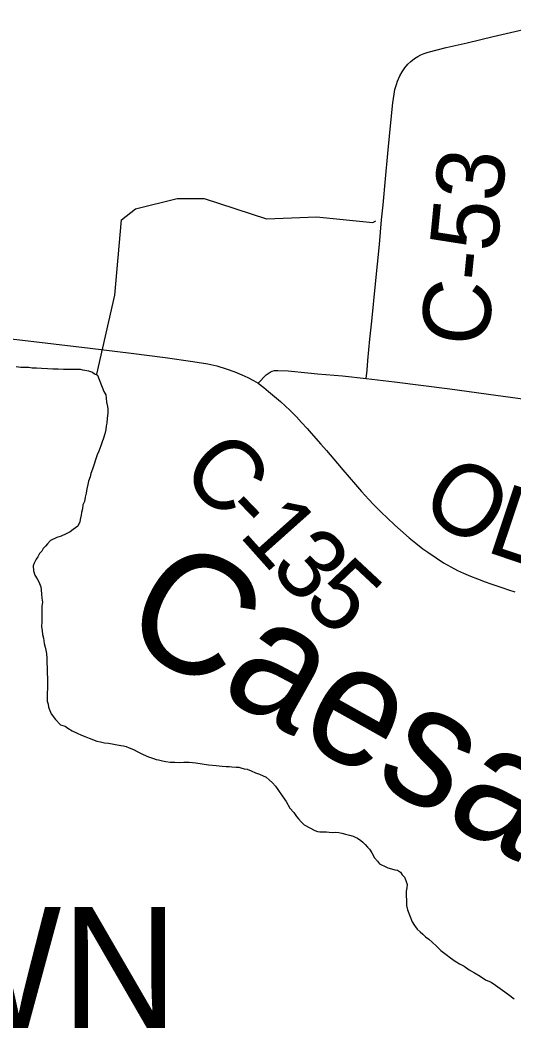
# Model space of a CAD drawing. Extents: x -13.9 to 69.1, y -25.2 to 26.1.
# Drawn here: x 4.71 to 5.08, y 17.195 to 17.95 of the extents above; entities that cross this region are included whole.
import ezdxf

# ---------------------------------------------------------------- set-up
doc = ezdxf.new("R2010")
doc.units = 0
for name, color, linetype in [('GM_X_Corporation_Text', 7, 'Continuous'), ('GM_X_County_Road', 7, 'Continuous'), ('GM_X_County_Road_Text', 7, 'Continuous'), ('GM_X_Minor_River', 7, 'Continuous'), ('GM_X_Minor_River_Text', 7, 'Continuous'), ('GM_X_State_Route', 7, 'Continuous')]:
    doc.layers.add(name, color=color, linetype=linetype)

msp = doc.modelspace()

# ---------------------------------------------------------------- linework, layer by layer
at = {"layer": 'GM_X_County_Road'}
for points in [[(4.9692, 17.68197), (4.9698, 17.68831), (4.97048, 17.69539), (4.97188, 17.71138), (4.97324, 17.72498), (4.97607, 17.75276), (4.97919, 17.78228), (4.98071, 17.80064), (4.98175, 17.81189), (4.98358, 17.83141), (4.98531, 17.85035), (4.98714, 17.86864), (4.98907, 17.88818), (4.99002, 17.8947), (4.99069, 17.89833), (4.99171, 17.90191), (4.99258, 17.90459), (4.99429, 17.90843), (4.99605, 17.91156), (4.99808, 17.91449), (5.00038, 17.91718), (5.00247, 17.91922), (5.00523, 17.9214), (5.0077, 17.9229), (5.0101, 17.92409), (5.01253, 17.92512), (5.01552, 17.92614), (5.02904, 17.92954), (5.04471, 17.93326), (5.06415, 17.93779), (5.11709, 17.9501)], [(4.88821, 17.67846), (4.89262, 17.67523), (4.89609, 17.67235), (4.89904, 17.66983), (4.90211, 17.66735), (4.90506, 17.66475), (4.90884, 17.66133), (4.91209, 17.65815), (4.91688, 17.65326), (4.92077, 17.64908), (4.92506, 17.64447), (4.92807, 17.64102), (4.93522, 17.63278), (4.9394, 17.62803), (4.94763, 17.61843), (4.95172, 17.61361), (4.96102, 17.60262), (4.96559, 17.59743), (4.97103, 17.59148), (4.97464, 17.58778), (4.9807, 17.58166), (4.98482, 17.57768), (4.99063, 17.57217), (4.99488, 17.56834), (5.00136, 17.56273), (5.00623, 17.55879), (5.01163, 17.55461), (5.01531, 17.55194), (5.02138, 17.54774), (5.0271, 17.54408), (5.03246, 17.54092), (5.03749, 17.53835), (5.04207, 17.53621), (5.04723, 17.53402), (5.05242, 17.53194), (5.05817, 17.52978), (5.06237, 17.52826), (5.06764, 17.52647), (5.07133, 17.52522), (5.07556, 17.52382), (5.08032, 17.52224)]]:
    msp.add_lwpolyline(points, dxfattribs=at)
at = {"layer": 'GM_X_Minor_River'}
for points in [[(4.76764, 17.68523), (4.78099, 17.74442), (4.78597, 17.80068), (4.79655, 17.80883), (4.8277, 17.81658), (4.84793, 17.81654), (4.89454, 17.80145), (4.93198, 17.8029), (4.97406, 17.7988), (4.97643, 17.79985)], [(4.70726, 17.69092), (4.71063, 17.69051), (4.71367, 17.69048), (4.71671, 17.69044), (4.71907, 17.69005), (4.72244, 17.69001), (4.72615, 17.6896), (4.73054, 17.68954), (4.73458, 17.68913), (4.73863, 17.68908), (4.74268, 17.68903), (4.74606, 17.68899), (4.74943, 17.68895), (4.75247, 17.68892), (4.75517, 17.68888), (4.75686, 17.6885), (4.75854, 17.68812), (4.76124, 17.68772), (4.76426, 17.68659), (4.76594, 17.68548), (4.76795, 17.68437), (4.7729, 17.6723), (4.77422, 17.66974), (4.77454, 17.66719), (4.77485, 17.66428), (4.77549, 17.661), (4.77581, 17.65918), (4.77577, 17.6559), (4.7754, 17.65227), (4.77503, 17.64864), (4.77467, 17.64646), (4.77431, 17.64392), (4.7736, 17.64066), (4.77255, 17.63739), (4.77151, 17.6345), (4.77047, 17.6316), (4.76908, 17.62762), (4.7677, 17.62472), (4.76665, 17.6211), (4.76561, 17.61784), (4.76422, 17.61422), (4.76318, 17.61096), (4.76248, 17.60842), (4.76143, 17.60516), (4.76073, 17.60262), (4.76003, 17.59936), (4.75966, 17.59609), (4.75895, 17.59319), (4.75825, 17.58993), (4.75721, 17.58739), (4.75684, 17.58449), (4.75614, 17.58159), (4.75578, 17.57977), (4.75508, 17.57651), (4.75472, 17.57469), (4.75334, 17.57144), (4.74994, 17.56893), (4.74756, 17.56714), (4.74451, 17.56573), (4.74077, 17.56395), (4.73773, 17.5629), (4.73298, 17.56078), (4.73059, 17.55826), (4.72923, 17.55646), (4.72752, 17.55466), (4.72649, 17.55285), (4.72478, 17.55105), (4.72341, 17.54852), (4.72204, 17.54672), (4.72066, 17.54383), (4.71997, 17.54166), (4.72027, 17.53802), (4.72125, 17.53473), (4.72291, 17.53216), (4.72391, 17.53033), (4.72456, 17.52851), (4.72555, 17.52595), (4.72587, 17.52377), (4.72617, 17.52049), (4.72648, 17.51757)], [(4.72648, 17.51757), (4.72679, 17.51466), (4.72642, 17.51139), (4.72638, 17.50812), (4.72636, 17.50557), (4.72633, 17.5023), (4.7263, 17.49976), (4.72627, 17.49648), (4.72658, 17.49321), (4.72688, 17.49029), (4.72754, 17.48774), (4.72785, 17.48556), (4.72817, 17.48373), (4.72882, 17.48082), (4.72947, 17.47863), (4.72978, 17.47607), (4.73008, 17.47244), (4.73006, 17.46953), (4.73035, 17.46516), (4.73031, 17.46116), (4.73062, 17.45788), (4.73053, 17.44952), (4.73051, 17.44697), (4.73049, 17.44479), (4.73047, 17.44261), (4.73044, 17.44043), (4.7311, 17.43824), (4.73141, 17.43605), (4.73339, 17.43094), (4.73672, 17.4269), (4.7404, 17.42285), (4.74376, 17.42172), (4.74577, 17.42024), (4.74913, 17.41838), (4.75282, 17.41652), (4.75618, 17.41502), (4.75921, 17.4139), (4.7619, 17.41277), (4.76392, 17.41202), (4.7656, 17.41127), (4.76762, 17.41052), (4.77031, 17.41013), (4.77334, 17.40936), (4.77638, 17.40896), (4.78548, 17.40739), (4.7875, 17.40701), (4.78952, 17.40662), (4.79187, 17.4055), (4.7949, 17.40437), (4.79825, 17.40251), (4.80229, 17.40064), (4.80632, 17.39878), (4.81002, 17.39764), (4.81204, 17.39689), (4.81372, 17.39651), (4.81675, 17.39574), (4.81911, 17.39535), (4.82248, 17.39495), (4.82586, 17.39491), (4.82923, 17.3945), (4.83261, 17.39482), (4.83666, 17.39477), (4.84172, 17.39435), (4.84644, 17.39356), (4.85115, 17.39278), (4.85689, 17.39235), (4.86127, 17.39193), (4.86431, 17.39153), (4.86667, 17.3915), (4.86869, 17.39148), (4.87173, 17.39108), (4.87375, 17.39105), (4.87544, 17.39067), (4.87779, 17.38991), (4.88015, 17.38952), (4.88318, 17.38839), (4.8862, 17.3869), (4.88923, 17.38577), (4.89427, 17.38353), (4.89661, 17.38168), (4.89896, 17.37947), (4.90129, 17.3769), (4.90362, 17.3736), (4.90628, 17.36956), (4.90928, 17.36553), (4.91193, 17.3604), (4.91493, 17.35709), (4.91693, 17.35416), (4.9186, 17.35232), (4.9206, 17.35012), (4.92261, 17.34791), (4.93067, 17.34381), (4.93269, 17.34306), (4.93437, 17.34268), (4.93775, 17.34264), (4.93943, 17.34262), (4.94146, 17.34259), (4.94382, 17.3422), (4.94585, 17.34254), (4.94854, 17.34214), (4.9509, 17.34175)], [(4.9509, 17.34175), (4.95359, 17.34099), (4.95662, 17.34023), (4.95932, 17.33947), (4.961, 17.33872), (4.96268, 17.33797), (4.96502, 17.33612), (4.9667, 17.33501), (4.96837, 17.33317), (4.97004, 17.33133), (4.97171, 17.32986), (4.97337, 17.32693), (4.97536, 17.32327), (4.9777, 17.3207), (4.97903, 17.31886), (4.98071, 17.31811), (4.98272, 17.317), (4.98542, 17.31588), (4.98811, 17.31512), (4.99046, 17.31436), (4.99249, 17.31397), (4.99483, 17.31249), (4.99616, 17.31065), (4.99783, 17.30881), (4.99882, 17.30626), (4.9998, 17.30333), (4.99944, 17.30079), (4.99908, 17.29825), (4.99905, 17.29498), (4.99935, 17.29134), (4.99931, 17.2877), (4.99996, 17.28442), (5.00358, 17.27529), (5.00524, 17.27272), (5.00724, 17.26979), (5.00958, 17.26794), (5.01159, 17.2661), (5.0136, 17.26426), (5.01594, 17.26241), (5.01862, 17.26019), (5.02163, 17.25725), (5.02497, 17.25394), (5.02899, 17.25098), (5.03234, 17.24839), (5.03569, 17.24581), (5.03905, 17.24395), (5.04241, 17.24209), (5.0461, 17.2395), (5.05012, 17.23727), (5.05449, 17.23467), (5.05851, 17.23207), (5.06254, 17.23021), (5.0659, 17.22798), (5.07126, 17.22428), (5.07562, 17.22096), (5.07997, 17.21763)]]:
    msp.add_lwpolyline(points, dxfattribs=at)
at = {"layer": 'GM_X_State_Route'}
for points in [[(4.65396, 17.71571), (4.65485, 17.71566), (4.65565, 17.71561), (4.68348, 17.71385), (4.70761, 17.71107), (4.76256, 17.7046), (4.79333, 17.70096), (4.81859, 17.69772), (4.83941, 17.69466), (4.85055, 17.69303), (4.85748, 17.69134), (4.86441, 17.68931), (4.87087, 17.68693), (4.87607, 17.68473), (4.88048, 17.68269), (4.88474, 17.68049), (4.88821, 17.67846)], [(4.88821, 17.67846), (4.89428, 17.68478), (4.89723, 17.68666), (4.89884, 17.68744), (4.90057, 17.68791), (4.90292, 17.68807), (4.91073, 17.68759), (4.92558, 17.68622), (4.93272, 17.68554), (4.95143, 17.68384), (4.96902, 17.68198), (4.9692, 17.68197), (4.99044, 17.67942), (5.03164, 17.67435), (5.06619, 17.66961), (5.0936, 17.66578)]]:
    msp.add_lwpolyline(points, dxfattribs=at)

# ---------------------------------------------------------------- texts
at = {"layer": 'GM_X_Corporation_Text'}
msp.add_text('JAMESTOWN', height=0.090639, rotation=0.00001, dxfattribs=at).set_placement((4.05418, 17.19585))
at = {"layer": 'GM_X_County_Road_Text'}
for s, height, rotation, p in [('C-53', 0.050591, 84.34643, (5.05976, 17.70481)), ('C', 0.0526, 314.57212, (4.82843, 17.61056)), ('O', 0.05338, 327.1179, (5.00714, 17.58334)), ('L', 0.05405, 341.51733, (5.05732, 17.55288)), ('-', 0.05256, 313.96977, (4.85852, 17.58001)), ('1', 0.05241, 311.73322, (4.8731, 17.56492)), ('3', 0.05252, 313.39782, (4.89579, 17.53951)), ('5', 0.05276, 316.9713, (4.92052, 17.51352))]:
    msp.add_text(s, height=height, rotation=rotation, dxfattribs=at).set_placement(p)
at = {"layer": 'GM_X_Minor_River_Text'}
msp.add_text('Caesar', height=0.089294, rotation=330.74227, dxfattribs=at).set_placement((4.78195, 17.48858))

doc.saveas('drawing.dxf')
